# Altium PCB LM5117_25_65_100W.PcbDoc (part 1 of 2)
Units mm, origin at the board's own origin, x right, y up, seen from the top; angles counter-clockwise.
Board outline 73.02 x 159.13 mm, 4 copper layers (Top Layer, GND, Power, Bottom Layer), stack 0.742 mm thick; 149 components, 80 nets, 535 pads, 514 vias.
Unrouted connection lines stored in the file: 2.
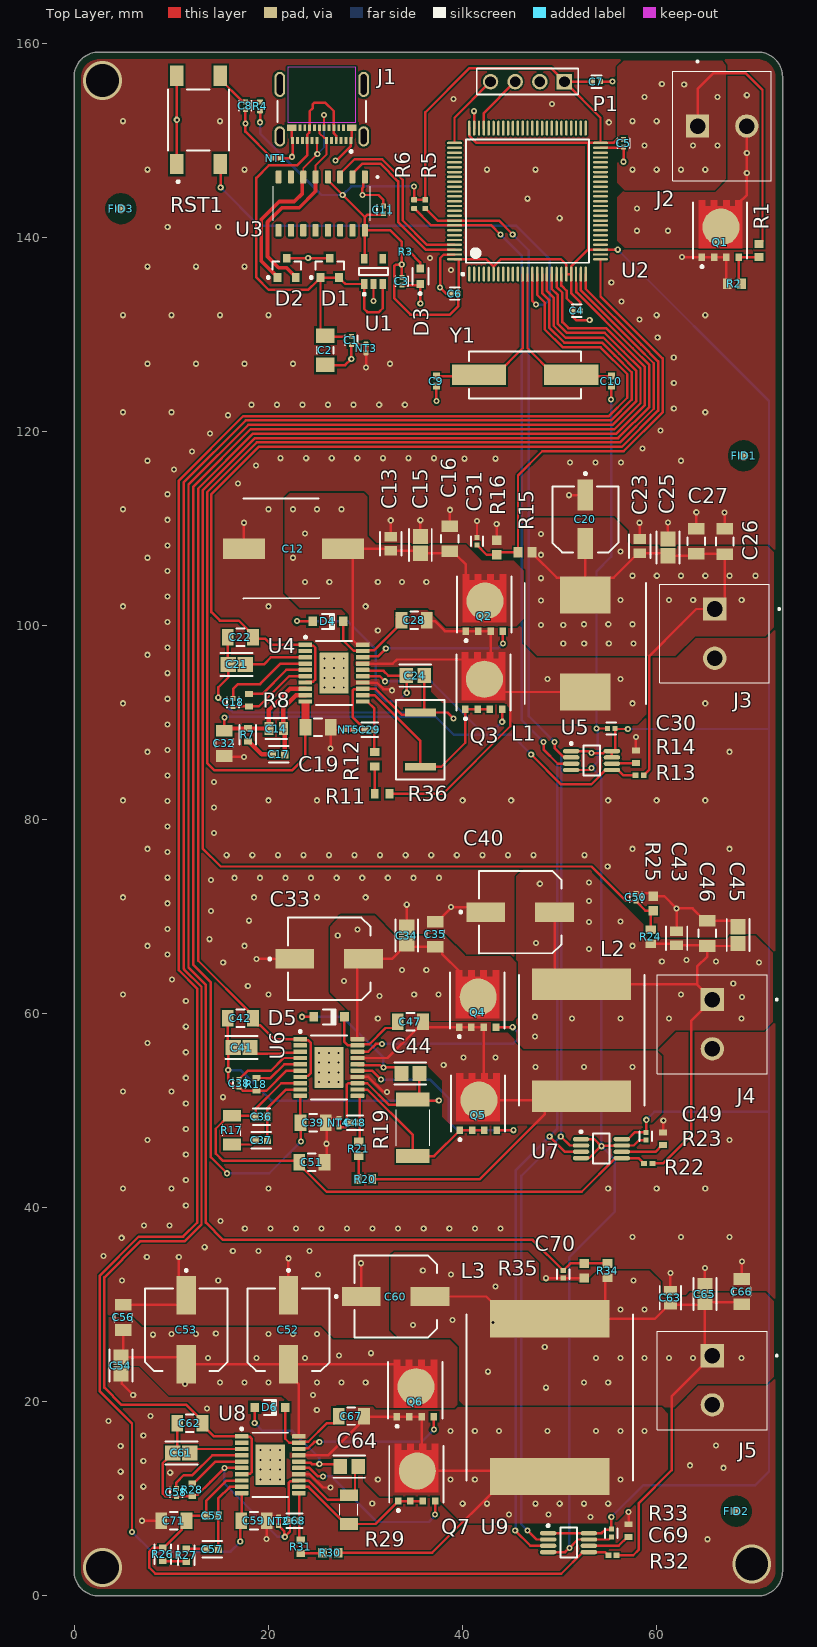
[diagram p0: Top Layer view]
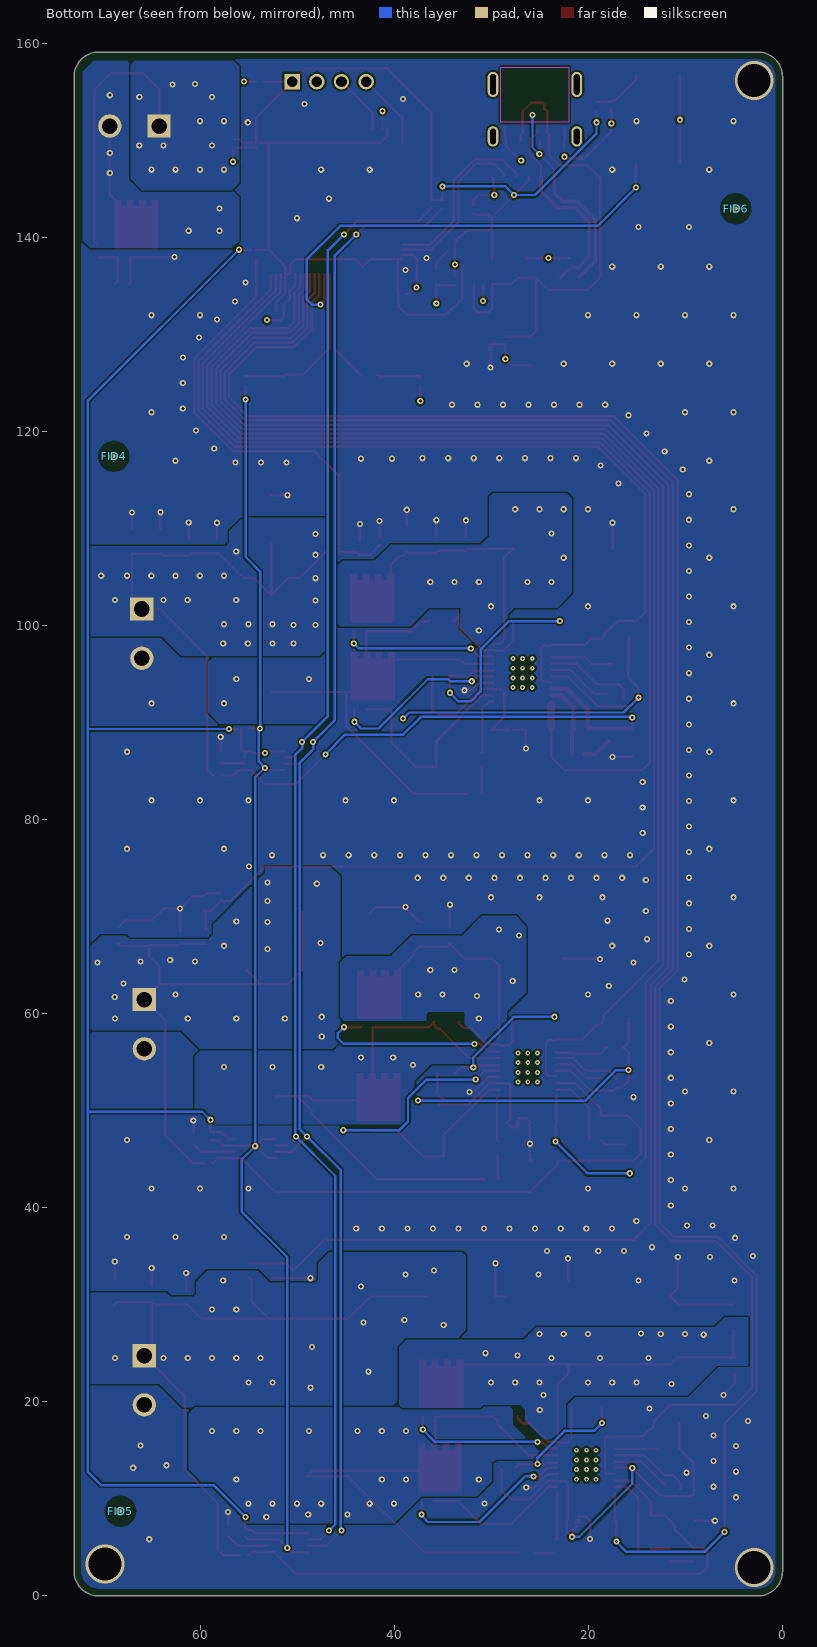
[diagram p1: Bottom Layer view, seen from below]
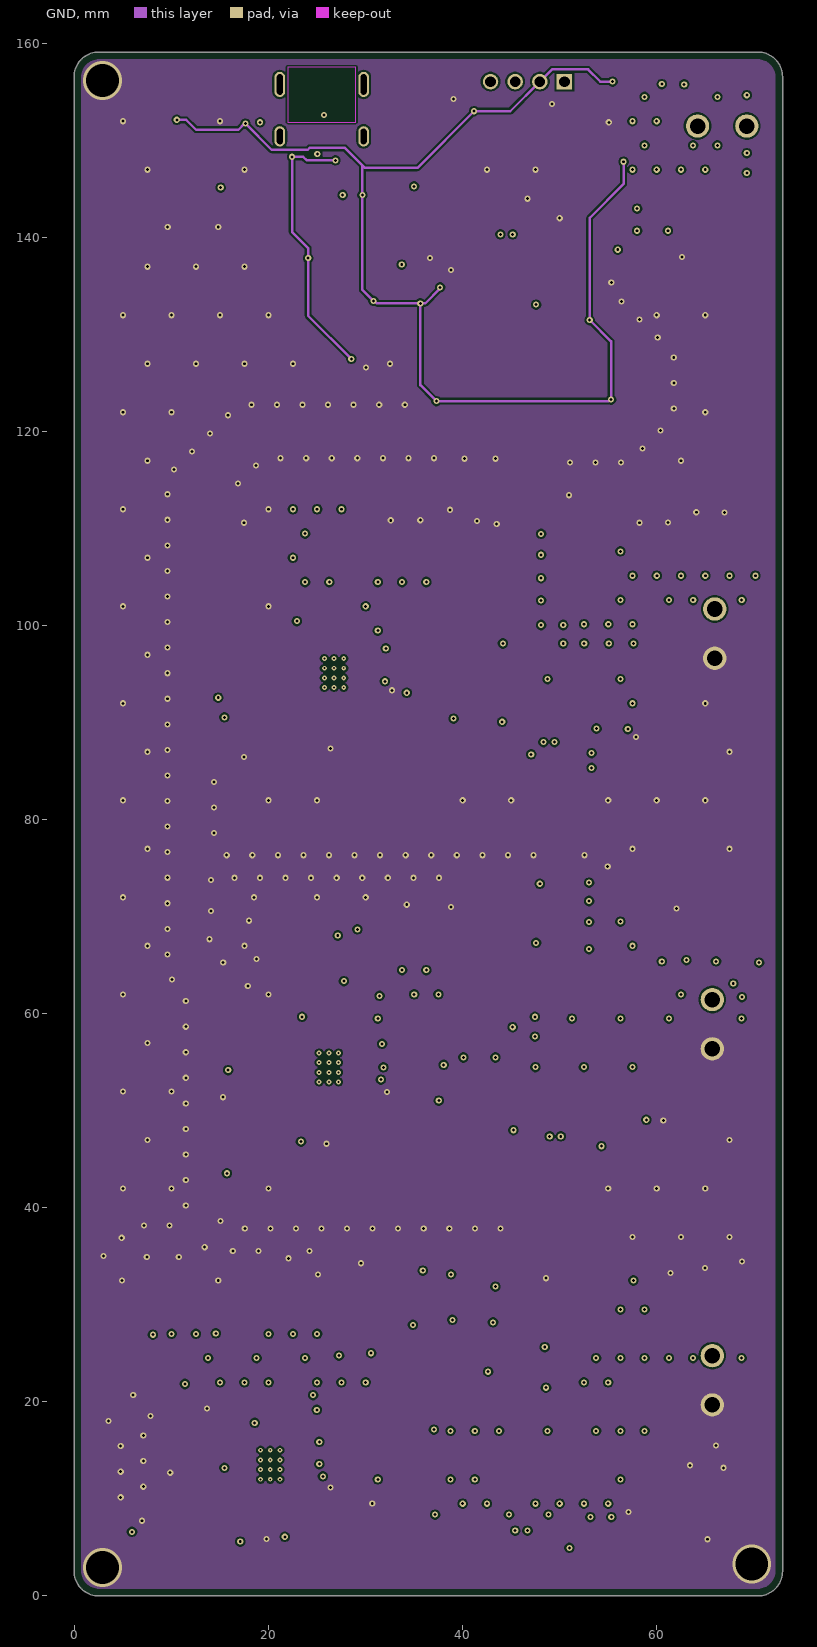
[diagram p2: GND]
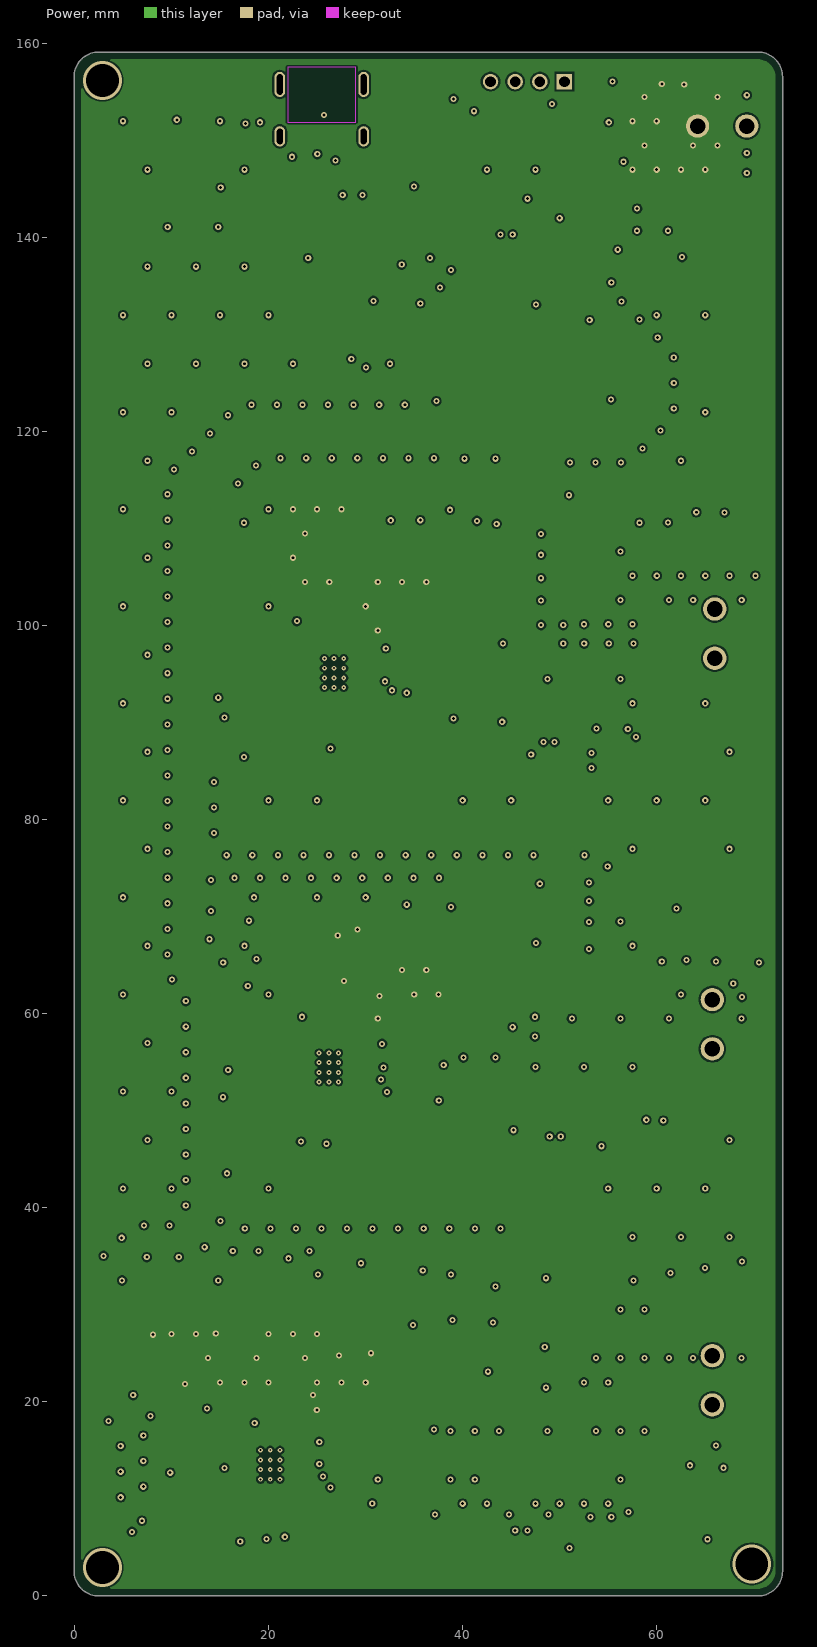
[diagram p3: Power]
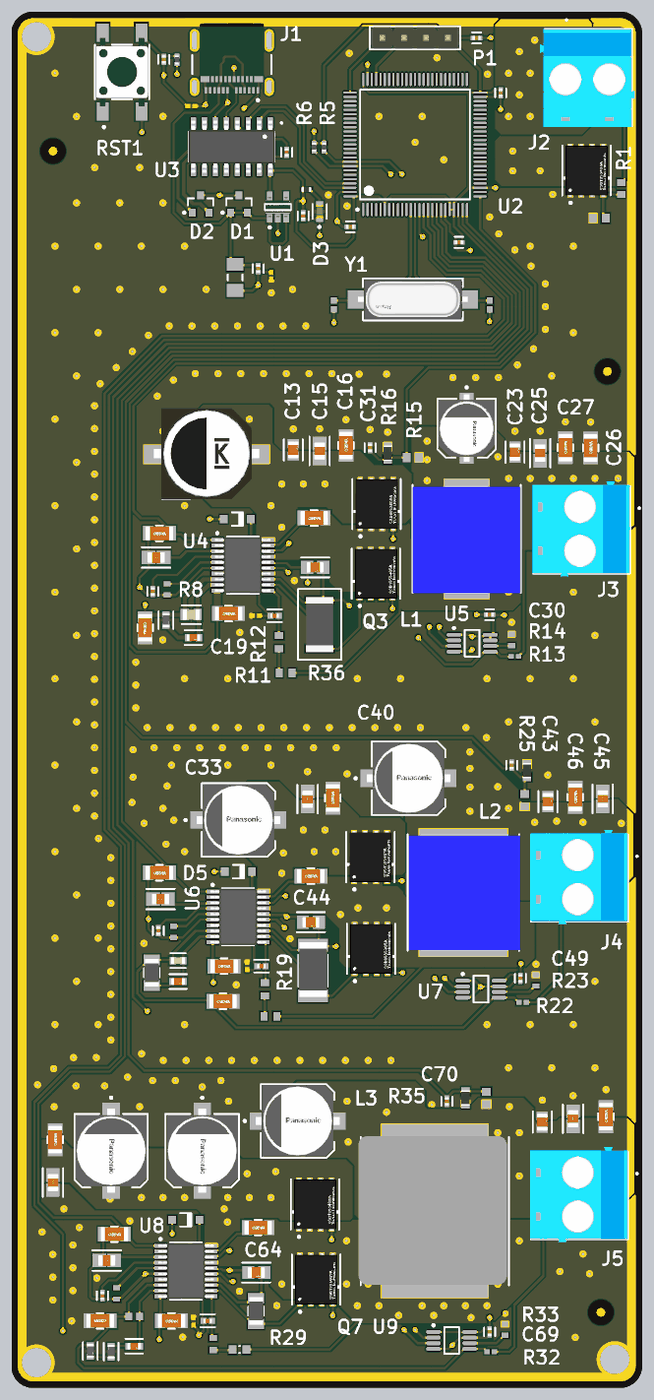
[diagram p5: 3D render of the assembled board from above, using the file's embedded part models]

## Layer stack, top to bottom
Top Solder: solder mask 0.0102, Solder Resist, Dk 3.5
Top Layer: signal copper 0.07
Dielectric 2: prepreg 0.0711, PP-006, Dk 4.1
GND: signal copper 0.07
Dielectric 1: dielectric 0.32, FR-4, Dk 4.8
Power: signal copper 0.07
Dielectric 3: prepreg 0.0711, PP-006, Dk 4.1
Bottom Layer: signal copper 0.07
Bottom Solder: solder mask 0.0102, Solder Resist, Dk 3.5

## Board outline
2.54,0 cw(c2.54,2.54) 0,2.54 0,156.591 cw(c2.54,156.591) 2.54,159.131 70.485,159.131 cw(c70.485,156.591) 73.025,156.591 73.025,2.54 cw(c70.485,2.54) 70.485,0

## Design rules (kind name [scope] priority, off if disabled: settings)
BoardOutlineClearance [All] p1: gap=0.75 ignorepadtopadclearanceinfootprint=FALSE
Clearance [All] p1: gap=0.2 ignorepadtopadclearanceinfootprint=TRUE
DiffPairsRouting [All] p1: maxlimit=0.254 minlimit=0.254 mostfreqgap=0.254 toplayer_minwidth=0.2 toplayer_maxwidth=0.381 toplayer_prefwidth=0.2 midlayer1_minwidth=0.2 midlayer1_maxwidth=0.381 midlayer1_prefwidth=0.381 midlayer2_minwidth=0.2 midlayer2_maxwidth=0.381 midlayer2_prefwidth=0.381 bottomlayer_minwidth=0.2 bottomlayer_maxwidth=0.381 bottomlayer_prefwidth=0.2 maxuncoupledlength=12.7
MinimumSolderMaskSliver [All] p1: minsoldermaskwidth=0.046
PlaneConnect [All] p1: planeconnectstyle=Direct reliefexpansion=0.508 reliefentries=4 reliefconductorwidth=0.254 reliefairgap=0.254
PolygonConnect [All] p1: connectstyle=Direct reliefconductorwidth=0.254 reliefentries=4 polygonreliefangle="90 Angle" airgapwidth=0.254
RoutingVias [All] p1: holewidth=0.711 width=1.27 viastyle="Through Hole" minholewidth=0.711 minwidth=1.27 maxholewidth=0.711 maxwidth=1.27
SilkToSolderMaskClearance [All] p1: minsilkscreentomaskgap=0.15 clearancetoexposedcopper=TRUE
SolderMaskExpansion [All] p1: expansion=0.102 istentingtop=FALSE
Width [All] p1: maxlimit=1 minlimit=0.254 preferedwidth=0.254
26 further rules are at their usual default settings.

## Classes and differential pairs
component class U_Programmer: C11 U3
component class "U_Power In": C1 C2 C3 D1 D2 D3 J1 J2 NT1 NT3 Q1 R1 R2 R3 U1
component class U_MCU: C4 C5 C6 C7 C8 C9 C10 P1 R4 R5 R6 RST1 U2 Y1
component class U_Buck_100W: C52 C53 C54 C55 C56 C57 C58 C59 C60 C61 C62 C63 C64 C65 C66 C67 C68 C69 C70 C71 D6 J5 L3 NT5 Q6 Q7 R26 R27 R28 R29 R30 R31 R32 R33 R34 R35 U8 U9
component class U_Buck_65W: C33 C34 C35 C36 C37 C38 C39 C40 C41 C42 C43 C44 C45 C46 C47 C48 C49 C50 C51 D5 J4 NT2 Q4 Q5 R17 R18 R19 R20 R21 R22 R23 R24 R25 U6 U7
component class U_Buck_25W: C12 C13 C14 C15 C16 C17 C18 C19 C20 C21 C22 C23 C24 C25 C26 C27 C28 C29 C30 C31 C32 D4 L1 NT2 Q2 Q3 R7 R8 R11 R12 R13 R14 R15 R16 R36 U4 U5
component class "Block Diagram": FID1 FID2 FID3 FID4 FID5 FID6
differential pair USB: +USB_P -USB_N

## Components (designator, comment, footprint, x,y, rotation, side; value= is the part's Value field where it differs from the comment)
C1 "C0402C104K4RACTU" FP-C0402-BB-MFG 28.575,129.413 r90 top value="0.10 μF"
C2 "C1206C105K3RACTU" CAPC3216X180X50ML20T25 25.908,128.397 r270 top
C3 "C0402C104K4RACTU" FP-C0402-BB-MFG 33.782,135.509 r90 top value="0.10 μF"
C4 "C0402C104K4RACTU" FP-C0402-BB-MFG 51.816,132.461 r0 top value="0.10 μF"
C5 "C0402C104K4RACTU" FP-C0402-BB-MFG 56.642,149.733 r90 top value="0.10 μF"
C6 "C0402C104K4RACTU" FP-C0402-BB-MFG 39.243,134.239 r0 top value="0.10 μF"
C7 "C0402C104K4RACTU" FP-C0402-BB-MFG 53.848,156.083 r180 top value="0.10 μF"
C8 "C0402C104K4RACTU" FP-C0402-BB-MFG 17.653,153.597 r90 top value="0.10 μF"
C9 "CC0402JRNPO9BN100" CAPC1005X55X25ML05T05 37.338,125.22 r270 top
C10 "CC0402JRNPO9BN100" CAPC1005X55X25ML05T05 55.372,125.222 r270 top
C11 "C0402C104K4RACTU" FP-C0402-BB-MFG 31.877,142.875 r270 top value="0.10 μF"
C12 "EDH476M100A9PAA" EDH476M100A9PAA 22.606,107.95 r180 top
C13 "GRM21BR61H475ME51L" FP-GRM21B-0_15-IPC_C 32.639,108.458 r90 top
C14 "C0805C680J5GAC" FP-C0805C-DN-MFG 20.828,89.408 r0 top value="68 pF"
C15 "C2012X7S2A105K125AB" FP-C2012-125-0_2-IPC_A 35.687,108.331 r90 top
C16 "CC1206KKX7R0BB104" FP-CC1206-0_3-1_45-IPC_C 38.735,108.966 r270 top
C17 "GCM188R72A682KA37D" FP-GCM188-0_1-IPC_C 21.082,86.741 r0 top
C18 "C0402C104K4RACTU" FP-C0402-BB-MFG 16.383,92.094 r270 top value="0.10 μF"
C19 "CC1206KKX7R0BB104" FP-CC1206-0_3-1_45-IPC_C 25.146,89.535 r180 top
C20 "EEE-FK1H100P" FP-FKD-MFG 52.705,110.958 r270 top
C21 "C2012X7S2A105K125AB" FP-C2012-125-0_2-IPC_A 16.764,96.012 r180 top
C22 "CC1206KKX7R0BB104" FP-CC1206-0_3-1_45-IPC_C 17.145,98.806 r180 top
C23 "GRM21BR61H475ME51L" FP-GRM21B-0_15-IPC_C 58.293,108.204 r90 top
C24 "GRM21BR72A474MA73L" FP-GRM21B-0_15-IPC_A 35.179,94.869 r0 top
C25 "C2012X7S2A105K125AB" FP-C2012-125-0_2-IPC_A 61.214,108.077 r90 top
C26 "CC1206KKX7R0BB104" FP-CC1206-0_3-1_45-IPC_C 67.056,108.682 r270 top
C27 "CC1206KKX7R0BB104" FP-CC1206-0_3-1_45-IPC_C 64.135,108.712 r270 top
C28 "CC1206KKX7R0BB104" FP-CC1206-0_3-1_45-IPC_C 35.052,100.584 r180 top
C29 "GCM155R72A821KA37J" FP-GCM155-0_05-IPC_A 30.48,89.281 r180 top
C30 "C0402C104K4RACTU" FP-C0402-BB-MFG 55.372,89.408 r180 top value="0.10 μF"
C31 "C0402C104K4RACTU" FP-C0402-BB-MFG 41.529,108.712 r270 top value="0.10 μF"
C32 "CC1206KKX7R0BB104" FP-CC1206-0_3-1_45-IPC_C 15.494,87.884 r90 top
C33 "EEE-TG2A220UP" FP-TGF-MFG 26.289,65.659 r0 top
C34 "C2012X7S2A105K125AB" FP-C2012-125-0_2-IPC_A 34.29,68.072 r90 top
C35 "CC1206KKX7R0BB104" FP-CC1206-0_3-1_45-IPC_C 37.211,68.199 r270 top
C36 "C0603C470J1GACTU" FP-C0603C-CF-MFG 19.304,49.403 r0 top value="47 pF"
C37 "GCM188R72A682KA37D" FP-GCM188-0_1-IPC_C 19.304,46.99 r0 top
C38 "C0402C104K4RACTU" FP-C0402-BB-MFG 17.018,52.851 r270 top value="0.10 μF"
C39 "CC1206KKX7R0BB104" FP-CC1206-0_3-1_45-IPC_C 24.638,48.768 r180 top
C40 "EEE-TG2A220UP" FP-TGF-MFG 45.974,70.485 r0 top
C41 "C2012X7S2A105K125AB" FP-C2012-125-0_2-IPC_A 17.272,56.515 r180 top
C42 "CC1206KKX7R0BB104" FP-CC1206-0_3-1_45-IPC_C 17.145,59.563 r180 top
C43 "GRM21BR61H475ME51L" FP-GRM21B-0_15-IPC_C 62.103,67.782 r90 top
C44 "GRM21BR72A474MA73L" FP-GRM21B-0_15-IPC_A 34.671,53.848 r0 top
C45 "C2012X7S2A105K125AB" FP-C2012-125-0_2-IPC_A 68.453,68.103 r90 top
C46 "CC1206KKX7R0BB104" FP-CC1206-0_3-1_45-IPC_C 65.278,68.29 r270 top
C47 "CC1206KKX7R0BB104" FP-CC1206-0_3-1_45-IPC_C 34.671,59.182 r180 top
C48 "GCM155R72A821KA37J" FP-GCM155-0_05-IPC_A 28.956,48.768 r180 top
C49 "C0402C104K4RACTU" FP-C0402-BB-MFG 58.928,47.371 r270 top value="0.10 μF"
C50 "C0402C104K4RACTU" FP-C0402-BB-MFG 57.912,72.009 r270 top value="0.10 μF"
C51 "CC1206KKX7R0BB104" FP-CC1206-0_3-1_45-IPC_C 24.511,44.704 r180 top
C52 "EEE-TG2A220UP" FP-TGF-MFG 22.098,27.432 r270 top
C53 "EEE-TG2A220UP" FP-TGF-MFG 11.557,27.432 r270 top
C54 "C2012X7S2A105K125AB" FP-C2012-125-0_2-IPC_A 4.826,23.749 r270 top
C55 "C0603C121J5GACTU" CAPC1608X87X35LL15T15 14.224,8.255 r0 top
C56 "CC1206KKX7R0BB104" FP-CC1206-0_3-1_45-IPC_C 5.08,28.702 r270 top
C57 "GCM188R72A682KA37D" FP-GCM188-0_1-IPC_C 14.224,4.826 r0 top
C58 "C0402C104K4RACTU" FP-C0402-BB-MFG 10.541,10.668 r270 top value="0.10 μF"
C59 "CC1206KKX7R0BB104" FP-CC1206-0_3-1_45-IPC_C 18.542,7.747 r180 top
C60 "EEE-TG2A220UP" FP-TGF-MFG 33.147,30.861 r0 top
C61 "C2012X7S2A105K125AB" FP-C2012-125-0_2-IPC_A 11.049,14.732 r180 top
C62 "CC1206KKX7R0BB104" FP-CC1206-0_3-1_45-IPC_C 11.938,17.78 r180 top
C63 "GRM21BR61H475ME51L" FP-GRM21B-0_15-IPC_C 61.468,30.734 r90 top
C64 "GRM21BR72A474MA73L" FP-GRM21B-0_15-IPC_A 28.358,13.335 r0 top
C65 "C2012X7S2A105K125AB" FP-C2012-125-0_2-IPC_A 65.024,31.115 r90 top
C66 "CC1206KKX7R0BB104" FP-CC1206-0_3-1_45-IPC_C 68.834,31.369 r270 top
C67 "CC1206KKX7R0BB104" FP-CC1206-0_3-1_45-IPC_C 28.575,18.542 r180 top
C68 "GCM155R72A821KA37J" FP-GCM155-0_05-IPC_A 22.733,7.747 r180 top
C69 "C0402C104K4RACTU" FP-C0402-BB-MFG 55.372,6.477 r270 top value="0.10 μF"
C70 "C0402C104K4RACTU" FP-C0402-BB-MFG 50.419,33.147 r90 top value="0.10 μF"
C71 "CC1206KKX7R0BB104" FP-CC1206-0_3-1_45-IPC_C 10.287,7.747 r0 top
D1 "SM15T1G" ONSC-SOT-23-3-318-08_V 26.35,136.89 r90 top
D2 "SM15T1G" ONSC-SOT-23-3-318-08_V 21.91,136.89 r90 top
D3 "150060VS75000" FP-150060VS75000-MFG 35.687,136.017 r90 top
D4 "1N4148W-7-F" DIOD-SOD123-2_V 26.162,100.457 r0 top
D5 "1N4148W-7-F" DIOD-SOD123-2_V 26.289,59.69 r0 top
D6 "1N4148W-7-F" DIOD-SOD123-2_V 20.193,19.431 r0 top
FID1 "FIDUCIAL" FIDUCIAL-ROUND 69.005,117.52 r0 top
FID2 "FIDUCIAL" FIDUCIAL-ROUND 68.243,8.732 r90 top
FID3 "FIDUCIAL" FIDUCIAL-ROUND 4.826,143.002 r90 top
FID4 "FIDUCIAL" FIDUCIAL-ROUND 68.929,117.452 r90 bottom
FID5 "FIDUCIAL" FIDUCIAL-ROUND 68.243,8.732 r90 bottom
FID6 "FIDUCIAL" FIDUCIAL-ROUND 4.826,143.002 r90 bottom
J1 "1054500101" FP-1054500101-MFG 25.527,153.797 r180 top locked
J2 "TB010-508-02BE" CUI_TB010-508-02BE 64.262,151.511 r0 top
J3 "TB010-508-02BE" CUI_TB010-508-02BE 66.04,101.727 r270 top
J4 "TB010-508-02BE" CUI_TB010-508-02BE 65.786,61.468 r270 top
J5 "TB010-508-02BE" CUI_TB010-508-02BE 65.786,24.765 r270 top
L1 "SRR1280-221K" SRR1280-221K 52.705,98.171 r90 top
L2 "IHLP5050EZER820M5A" IHLP5050EZER820M5A 52.324,57.277 r90 top
L3 "IHLP6767DZER470M11" IHLP6767DZER470M11 49.022,20.447 r90 top
NT1 "BOARD FEATURE" NETTIE-0.5X0.5X0.4 20.828,148.209 r0 top net-tie
NT2 "BOARD FEATURE" NETTIE-0.5X0.5X0.4 21.082,7.689 r90 top net-tie
NT3 "BOARD FEATURE" NETTIE-0.5X0.5X0.4 30.099,128.582 r270 top net-tie
NT4 "BOARD FEATURE" NETTIE-0.5X0.5X0.4 27.305,48.768 r90 top net-tie
NT5 "BOARD FEATURE" NETTIE-0.5X0.5X0.4 28.321,89.281 r180 top net-tie
P1 "61300411121" 61300411121 46.736,156.083 r180 top
Q1 "CSD19534Q5A" FP-DQJ0008A-MFG 66.605,140.747 r90 top
Q2 "CSD19534Q5AT" FP-DQJ0008A-MFG 42.291,102.193 r90 top
Q3 "CSD19534Q5AT" FP-DQJ0008A-MFG 42.221,94.138 r90 top
Q4 "CSD19534Q5AT" FP-DQJ0008A-MFG 41.586,61.372 r90 top
Q5 "CSD19534Q5AT" FP-DQJ0008A-MFG 41.656,50.758 r90 top
Q6 "CSD19534Q5AT" FP-DQJ0008A-MFG 35.179,21.209 r90 top
Q7 "CSD19534Q5AT" FP-DQJ0008A-MFG 35.306,12.531 r90 top
R1 "ERJ-3GEYJ104V" RESC1608X55X30NL15T15 70.612,138.684 r90 top
R2 "ERJ-3EKF2002V" RESC1608X55X30ML15T15 68.072,135.255 r0 top
R3 "ERJ-2RKF1000X" RESC1005X40X25LL05T05 34.163,138.557 r180 top
R4 "CRCW04023K30JNED" RESC1005X55N 19.177,153.543 r270 top value=3K3
R5 "CRCW04023K30JNED" RESC1005X55N 36.195,143.452 r270 top value=3K3
R6 "CRCW04023K30JNED" RESC1005X55N 35.052,143.452 r270 top value=3K3
R7 "RC0603FR-0736KL" FP-RC0603-0_55-IPC_C 17.907,88.773 r270 top
R8 "RC0603FR-0715KL" RESC1608X55X25LL10T15 18.034,92.329 r90 top
R11 "RC0603JR-07270KL" RESC1608X55X25ML10T15 31.75,82.677 r0 top
R12 "RC0603JR-1310KL" RESC1608X55X25ML10T15 30.988,86.233 r270 top
R13 "RC0402FR-0743KL" RESC1005X40X25NL05T10 58.293,84.582 r0 top
R14 "RC0603FR-0733RL" RESC1608X55X25LL10T15 57.912,86.487 r90 top
R15 "ERJ-3EKF1003V" RESC1608X55X30ML15T15 46.482,107.569 r0 top
R16 "ERJ-3EKF6801V" RESC1609X55X30NL15T15 43.561,108.065 r270 top
R17 "RC0603FR-0786K6L" PE1206FRM470R02L 16.256,48.006 r270 top value="86.6 kOhm"
R18 "RC0603FR-0715KL" RESC1608X55X25LL10T15 18.796,52.724 r90 top
R19 "PE2512FKE070R033L" PE2512FKE070R033L 34.925,48.255 r270 top value=33mOh
R20 "RC0603FR-10300KL" RESC1608X55X25ML10T15 29.987,42.968 r0 top
R21 "RC0603FR-103KL" RESC1608X55X25ML10T15 29.337,46.101 r270 top
R22 "RC0402FR-0743KL" RESC1005X40X25NL05T10 59.182,44.577 r0 top
R23 "RC0603FR-0733RL" RESC1608X55X25LL10T15 60.706,47.117 r90 top
R24 "ERJ-3EKF1003V" RESC1608X55X30ML15T15 59.436,67.945 r270 top
R25 "ERJ-3EKF6801V" RESC1609X55X30NL15T15 59.69,71.374 r270 top
R26 "RC0603FR-0736KL" FP-RC0603-0_55-IPC_C 9.144,4.276 r270 top
R27 "RC0603FR-071KL" FP-RC0603-0_55-IPC_C 11.557,4.191 r90 top
R28 "RC0603FR-0715KL" RESC1608X55X25LL10T15 12.192,10.922 r90 top
R29 "PE1206FRM470R02L" PE1206FRM470R02L 28.321,8.89 r270 top
R30 "RC0603FR-07270KL" RESC0603(1608)_N 26.416,4.445 r0 top value="270 kOhm"
R31 "RC0603FR-073KL" RESC1608X55X25NL10T15 23.368,5.08 r270 top
R32 "RC0402FR-0743KL" RESC1005X40X25NL05T10 55.499,4.191 r0 top
R33 "RC0603FR-0733RL" RESC1608X55X25LL10T15 57.15,6.731 r90 top
R34 "ERJ-3EKF1003V" RESC1608X55X30ML15T15 54.991,33.528 r270 top
R35 "ERJ-3EKF6801V" RESC1609X55X30NL15T15 52.578,33.528 r90 top
R36 "WSL2512R0900FEA" WSL2512R0900FEA 35.687,88.265 r270 top
RST1 "FSM2JSMAA" FP-FSM2JSMAA-MFG 12.827,152.146 r180 top
U1 "MIC5504-3.3YM5-TR" FP-SOT23-5LD-PL-1-MFG 30.861,136.525 r90 top
U2 "STM32F303VET7" STM-LQFP100_L 46.736,143.764 r90 top
U3 "CH340C" SOIC127P600X180-16N 25.527,143.51 r270 top
U4 "LM5117PMH/NOPB" PWP0020A_N 26.797,95.123 r0 top
U5 "MCP4552-502E/MS" MSOP-MS8_N 53.34,86.106 r0 top
U6 "LM5117PMH/NOPB" PWP0020A_N 26.259,54.469 r0 top
U7 "MCP4552-502E/MS" MSOP-MS8_N 54.356,46.101 r0 top
U8 "LM5117PMH/NOPB" PWP0020A_N 20.222,13.518 r0 top
U9 "MCP4552-502E/MS" MSOP-MS8_N 50.967,5.491 r0 top
Y1 "ABLS-8.000MHZ-B2-T" FP-ABLS-MFG 46.482,125.857 r180 top

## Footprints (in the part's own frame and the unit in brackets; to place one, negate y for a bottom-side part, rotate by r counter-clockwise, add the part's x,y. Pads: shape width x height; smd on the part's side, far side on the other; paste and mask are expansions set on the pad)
61300411121 [mm] "Pin Header, pitch 2.54 mm, THT, Vertical, single row, 4p"
  rect 1.6x1.6 hole 1.1: 1(-3.81,0)
  round 1.6 hole 1.1: 2(-1.27,0) 3(1.27,0) 4(3.81,0)
  silkscreen extent -5.23,-1.35 5.23,1.35, body extent -5.08,-1.27 5.08,1.27, height 8.57
CAPC1005X55X25ML05T05 [mm] "Chip Capacitor, 2-Leads, Body 1.00x0.50mm, IPC Low Density"
  rect 0.72x0.72 smd: 1(-0.51,0) 2(0.51,0)
  body extent -0.53,-0.28 0.53,0.27, height 0.55
CAPC1608X87X35LL15T15 [mm] "Chip Capacitor, 2-Leads, Body 1.60x0.80mm, IPC High Density"
  rect 0.8x0.9 smd: 1(-0.625,0) 2(0.625,0)
  body extent -0.87,-0.48 0.87,0.48, height 0.87
CAPC3216X180X50ML20T25 [mm] "Chip Capacitor, 2-Leads, Body 3.40x1.80mm, IPC Low Density"
  rect 1.5x1.9 smd: 1(-1.5,0) 2(1.5,0)
  silkscreen extent -0.35,-0.85 0.35,0.85, body extent -1.7,-0.9 1.7,0.9, height 1.8
CUI_TB010-508-02BE [mm]
  rect 2.4x2.4 / inner round 2.4 / far side rect 2.4x2.4 hole 1.6: 1(0,0)
  round 2.4 hole 1.6: 2(5.08,0)
  silkscreen extent -2.54,-5.66 7.62,6.74, body extent -3.07,-5.71 7.89,5.58, height 18.2
DIOD-SOD123-2_V [mm] "SOD123, 2-Leads, Body 2.7x1.55mm, Height 1.45mm"
  rect 0.9x0.95 smd: 1(-1.575,0) 2(1.575,0)
  silkscreen extent -0.64,-0.82 0.64,0.77, body extent -1.35,-0.77 1.35,0.77, height 1.45
EDH476M100A9PAA [mm]
  rect 4.35x2.1 smd: 1(-5.1,0) 2(5.1,0)
  silkscreen extent -2.67,-5.15 5.15,5.15, body extent -6.1,-5.33 6.1,5.17, height 10.51
FIDUCIAL-ROUND [mm] "BOARD FEATURE FIDUCIAL TARGET ROUND 1MM , 3MM CLEARANCE"
  round 1 smd paste-0.5 mask+1: 1(0,0)
  Top Layer pour cut-out: -0.025,-1.601 -0.632,-1.475 -1.144,-1.127 -1.484,-0.609 -1.6,0 -1.6,0 -1.478,0.612 -1.131,1.131 -0.612,1.478 0,1.6 0,1.6 0.612,1.478 1.131,1.131 1.478,0.612 1.6,0 1.6,0 1.473,-0.616 1.119,-1.137 0.593,-1.483 -0.025,-1.601
FP-150060VS75000-MFG [mm]
  rect 0.8x0.8 smd paste+0 mask+0: 1(-0.8,0) 2(0.8,0)
  silkscreen extent -1.9,-0.83 0.85,0.82, body extent -1.3,-0.55 1.3,0.55, height 0.25
FP-1054500101-MFG [mm]
  rrect100% 1.1x2.1 hole 1.6 slot 0.6 at 0 deg paste-1000 mask+0: 1(-4.32,3.36) 2(4.32,3.36)
  rrect100% 1.1x2.6 hole 2.1 slot 0.6 at 0 deg paste-1000 mask+0: 3(-4.32,-2) 4(4.32,-2)
  rect 0.3x0.7 smd paste+0 mask+0: A1(-3,3.77) A2(-2.5,3.77) A3(-2,3.77) A4(-1.5,3.77) A5(-1,3.77) A6(-0.5,3.77) A7(0.5,3.77) A8(1,3.77) A9(1.5,3.77) A10(2,3.77) A11(2.5,3.77) A12(3,3.77) B2(2.25,2.47) B3(1.75,2.47) B4(1.25,2.47) B5(0.75,2.47) B6(0.25,2.47) B7(-0.25,2.47) B8(-0.75,2.47) B9(-1.25,2.47) B10(-1.75,2.47) B11(-2.25,2.47)
  rect 1x0.7 smd paste+0 mask+0: B1(3.1,2.47) B12(-3.1,2.47)
  Keep-Out Layer region: -3.5,-3.77 3.5,-3.77 3.5,1.88 -3.5,1.88
  silkscreen extent -4.57,-0.3 4.57,5.03
FP-ABLS-MFG [mm]
  rect 5.6x2.1 smd paste+0 mask+0: 1(-4.75,0) 2(4.75,0)
  silkscreen extent -5.77,-2.42 5.77,2.42, body extent -7.65,-2.52 7.65,2.52, height 0.25
FP-C0402-BB-MFG [mm]
  rect 0.52x0.52 smd paste+0 mask+0: 1(-0.4,0) 2(0.4,0)
  silkscreen extent -0.5,-0.64 0.5,0.64, body extent -0.8,-0.4 0.8,0.4, height 0.25
FP-C0603C-CF-MFG [mm]
  rect 0.75x0.9 smd paste+0 mask+0: 1(-0.6,0) 2(0.6,0)
  silkscreen extent -0.87,-0.85 0.88,0.85, body extent -1.2,-0.6 1.2,0.6, height 0.25
FP-C0805C-DN-MFG [mm]
  rect 0.95x1.35 smd paste+0 mask+0: 1(-0.75,0) 2(0.75,0)
  silkscreen extent -1.1,-1.07 1.1,1.07, body extent -1.4,-0.85 1.4,0.85, height 0.25
FP-C2012-125-0_2-IPC_A [mm]
  rect 1.578x1.556 smd paste+0 mask+0: 1(-0.864,0) 2(0.864,0)
  silkscreen extent -1.65,-1.18 1.65,1.18, body extent -2.15,-1.28 2.15,1.28, height 0.25
FP-CC1206-0_3-1_45-IPC_C [mm]
  rect 1.203x1.706 smd paste+0 mask+0: 1(-1.3,0) 2(1.3,0)
  silkscreen extent -0.4,-0.9 0.4,0.9, body extent -2,-1 2,1, height 0.25
FP-DQJ0008A-MFG [mm]
  rect 0.75x0.675 smd paste-1000 mask+0: 1(-2.752,1.905) 2(-2.752,0.635) 3(-2.752,-0.635) 4(-2.752,-1.905)
  round 3.821 smd paste-1000 mask+0: 5-6-7-8(0.35,-0.07)
  Top Layer region: -1.823,2.242 3.127,2.242 3.127,1.568 2.472,1.568 2.472,0.972 3.127,0.972 3.127,0.298 2.472,0.298 2.472,-0.298 3.127,-0.298 3.127,-0.972 2.472,-0.972 2.472,-1.568 3.127,-1.568 3.127,-2.242 -1.823,-2.242 -1.823,2.242
  silkscreen extent -3.85,-2.78 2.9,2.82, body extent -3.23,-2.6 3.23,2.6, height 0.25
FP-FKD-MFG [mm]
  rect 3.2x1.6 smd paste+0 mask+0: 1(-2.5,0) 2(2.5,0)
  silkscreen extent -4.85,-3.4 3.4,3.4, body extent -4.35,-3.65 4.35,3.65, height 0.25
FP-FSM2JSMAA-MFG [mm]
  rect 1.38x2.1 smd paste+0 mask+0: 1(2.25,4.55) 2(2.24,-4.55) 3(-2.24,4.55) 4(-2.24,-4.55)
  silkscreen extent -3.15,-3.15 3.15,6.5, body extent -3.25,-5.7 3.25,5.7, height 0.25
FP-GCM155-0_05-IPC_A [mm]
  rect 0.715x0.672 smd paste+0 mask+0: 1(-0.479,0) 2(0.479,0)
  silkscreen extent -0.84,-0.74 0.84,0.74, body extent -1.04,-0.54 1.04,0.54, height 0.25
FP-GCM188-0_1-IPC_C [mm]
  rect 0.759x0.812 smd paste+0 mask+0: 1(-0.627,0) 2(0.627,0)
  silkscreen extent -1.01,-0.85 1.01,0.85, body extent -1.11,-0.55 1.11,0.55, height 0.25
FP-GRM21B-0_15-IPC_A [mm]
  rect 1.406x1.508 smd paste+0 mask+0: 1(-0.926,0) 2(0.926,0)
  silkscreen extent -1.63,-1.15 1.63,1.15, body extent -2.13,-1.25 2.13,1.25, height 0.25
FP-GRM21B-0_15-IPC_C [mm]
  rect 1.006x1.308 smd paste+0 mask+0: 1(-0.726,0) 2(0.726,0)
  silkscreen extent -1.23,-1.1 1.23,1.1, body extent -1.33,-0.8 1.33,0.8, height 0.25
FP-RC0603-0_55-IPC_C [mm]
  rect 0.659x0.812 smd paste+0 mask+0: 1(-0.677,0) 2(0.677,0)
  silkscreen extent -1.01,-0.85 1.01,0.85, body extent -1.11,-0.55 1.11,0.55, height 0.25
FP-SOT23-5LD-PL-1-MFG [mm]
  rect 1x0.66 smd paste+0 mask+0: 1(-1.3,0.95) 2(-1.3,0) 3(-1.3,-0.95) 4(1.3,-0.95) 5(1.3,0.95)
  silkscreen extent -2.47,-1.5 0.35,1.5, body extent -1.9,-1.6 1.9,1.6, height 0.25
FP-TGF-MFG [mm]
  rect 4x2 smd paste+0 mask+0: 1(-3.55,0) 2(3.55,0)
  silkscreen extent -6.25,-4.25 4.25,4.25, body extent -5.8,-4.5 5.8,4.5, height 0.25
IHLP5050EZER820M5A [mm]
  rect 3.25x10.2 smd: 1(-5.75,0) 2(5.75,0)
  silkscreen extent -6.73,-6.45 6.73,6.45, body extent -6.73,-6.58 6.73,6.32, height 5
IHLP6767DZER470M11 [mm]
  rect 3.825x12.32 smd: 1(-8.123,0) 2(8.123,0)
  silkscreen extent -8.57,-8.57 8.57,8.57, body extent -8.51,-8.34 8.67,8.84, height 3.9
MSOP-MS8_N [mm] "TSOP, 8-Leads, Body 3x3mm, Pitch 0.65mm, IPC Medium Density"
  oval 1.7x0.45 smd: 1(-2.1,0.975) 2(-2.1,0.325) 3(-2.1,-0.325) 4(-2.1,-0.975) 5(2.1,-0.975) 6(2.1,-0.325) 7(2.1,0.325) 8(2.1,0.975)
  silkscreen extent -2.22,-1.55 0.85,1.87, body extent -1.55,-1.55 1.55,1.55, height 1.1
NETTIE-0.5X0.5X0.4 [mm] "NET TIE 0.5 X 0.5MM PAD, 0.4MM GAP"
  rrect25% 0.5x0.5 smd paste-4 mask+0.076: 1(-0.45,0) 2(0.45,0)
  Top Layer region: -0.275,-0.25 0.25,-0.25 0.25,0.25 -0.275,0.25
ONSC-SOT-23-3-318-08_V [mm] "SOT23, 3-Leads, Body 2.92x1.3mm, Pitch 0.95mm"
  rect 0.9x0.8 smd: 1(-1,0.95) 2(-1,-0.95) 3(1,0)
  silkscreen extent -1.12,-1.46 0.65,2.02, body extent -0.65,-1.46 0.65,1.46, height 1.11
PE1206FRM470R02L [mm]
  rect 1.21x1.86 smd: 1(-1.476,0) 2(1.476,0)
  silkscreen extent -0.55,-0.93 0.55,0.93, body extent -1.6,-0.8 1.6,0.8, height 0.89
PE2512FKE070R033L [mm]
  rect 1.46x3.44 smd: 1(-2.926,0) 2(2.926,0)
  silkscreen extent -1.87,-1.72 1.87,1.72, body extent -3.3,-1.59 3.05,1.59, height 0.89
PWP0020A_N [mm] "SOP, 20-Leads, Body 6.6x4.5mm, Pitch 0.65mm, Thermal Pad 4.2x3mm, IPC Medium Density"
  rrect22% 1.4x0.45 smd: 1(-2.95,2.925) 2(-2.95,2.275) 3(-2.95,1.625) 4(-2.95,0.975) 5(-2.95,0.325) 6(-2.95,-0.325) 7(-2.95,-0.975) 8(-2.95,-1.625) 9(-2.95,-2.275) 10(-2.95,-2.925) 11(2.95,-2.925) 12(2.95,-2.275) 13(2.95,-1.625) 14(2.95,-0.975) 15(2.95,-0.325) 16(2.95,0.325) 17(2.95,0.975) 18(2.95,1.625) 19(2.95,2.275) 20(2.95,2.925)
  rrect3% 3x4.2 smd: 21(0,0)
  silkscreen extent -3.07,-3.3 1.85,3.82, body extent -3.21,-3.25 3.21,3.25, height 1
RESC0603(1608)_N [mm] "Chip Resistor, Body 1.6x0.8mm, IPC Medium Density"
  rect 0.9x1 smd: 1(-0.8,0) 2(0.8,0)
  silkscreen extent -0.05,-0.4 0.05,0.4, body extent -0.85,-0.47 0.85,0.47, height 0.6
RESC1005X40X25LL05T05 [mm] "Chip Resistor, 2-Leads, Body 1.05x0.55mm, IPC High Density"
  rect 0.45x0.45 smd: 1(-0.4,0) 2(0.4,0)
  body extent -0.53,-0.28 0.53,0.28, height 0.4
RESC1005X40X25NL05T10 [mm] "Chip Resistor, 2-Leads, Body 1.00x0.50mm, IPC Medium Density"
  rect 0.6x0.55 smd: 1(-0.425,0) 2(0.425,0)
  body extent -0.53,-0.27 0.53,0.28, height 0.4
RESC1005X55N [mm] "RESISTOR CHIP 0402 (1005) 0.55MM THICK"
  rrect25% 0.55x0.6 smd mask+0.075: 1(-0.45,0) 2(0.45,0)
  body extent -0.5,-0.25 0.5,0.25, height 0.27
RESC1608X55X25LL10T15 [mm] "Chip Resistor, 2-Leads, Body 1.70x0.90mm, IPC High Density"
  rect 0.6x0.8 smd: 1(-0.65,0) 2(0.65,0)
  body extent -0.85,-0.45 0.85,0.45, height 0.55
RESC1608X55X25ML10T15 [mm] "Chip Resistor, 2-Leads, Body 1.60x0.80mm, IPC Low Density"
  rect 0.8x1 smd: 1(-0.75,0) 2(0.75,0)
  body extent -0.85,-0.45 0.85,0.45, height 0.55
RESC1608X55X25NL10T15 [mm] "Chip Resistor, 2-Leads, Body 1.60x0.80mm, IPC Medium Density"
  rect 0.7x0.9 smd: 1(-0.7,0) 2(0.7,0)
  body extent -0.85,-0.45 0.85,0.45, height 0.55
RESC1608X55X30ML15T15 [mm] "Chip Resistor, 2-Leads, Body 1.60x0.80mm, IPC Low Density"
  rect 0.9x1.05 smd: 1(-0.725,0) 2(0.725,0)
  body extent -0.87,-0.48 0.87,0.48, height 0.55
RESC1608X55X30NL15T15 [mm] "Chip Resistor, 2-Leads, Body 1.60x0.80mm, IPC Medium Density"
  rect 0.8x0.95 smd: 1(-0.675,0) 2(0.675,0)
  body extent -0.87,-0.48 0.87,0.48, height 0.55
RESC1609X55X30NL15T15 [mm] "Chip Resistor, 2-Leads, Body 1.75x0.95mm, IPC Medium Density"
  rect 0.95x0.95 smd: 1(-0.75,0) 2(0.75,0)
  body extent -0.87,-0.48 0.87,0.48, height 0.55
SOIC127P600X180-16N [mm]
  rrect25% 1.31x0.62 smd: 1(-2.75,4.445) 2(-2.75,3.175) 3(-2.75,1.905) 4(-2.75,0.635) 5(-2.75,-0.635) 6(-2.75,-1.905) 7(-2.75,-3.175) 8(-2.75,-4.445) 9(2.75,-4.445) 10(2.75,-3.175) 11(2.75,-1.905) 12(2.75,-0.635) 13(2.75,0.635) 14(2.75,1.905) 15(2.75,3.175) 16(2.75,4.445)
  silkscreen extent -2.85,-5 1.78,5.85, body extent -3,-5 3,5, height 1.8
SRR1280-221K [mm]
  rect 3.8x5.2 smd: 1(-5,0) 2(5,0)
  silkscreen extent -6.25,-6.25 6.25,6.25, body extent -6.38,-6.25 6.12,6.25, height 8
STM-LQFP100_L [mm] "Thin QFP, 100-Leads, Body 14x14mm, Pitch 0.5mm, IPC High Density"
  oval 1.55x0.25 smd: 1(-7.525,6) 2(-7.525,5.5) 3(-7.525,5) 4(-7.525,4.5) 5(-7.525,4) 6(-7.525,3.5) 7(-7.525,3) 8(-7.525,2.5) 9(-7.525,2) 10(-7.525,1.5) 11(-7.525,1) 12(-7.525,0.5) 13(-7.525,0) 14(-7.525,-0.5) 15(-7.525,-1) 16(-7.525,-1.5) 17(-7.525,-2) 18(-7.525,-2.5) 19(-7.525,-3) 20(-7.525,-3.5) 21(-7.525,-4) 22(-7.525,-4.5) 23(-7.525,-5) 24(-7.525,-5.5) 25(-7.525,-6) 51(7.525,-6) 52(7.525,-5.5) 53(7.525,-5) 54(7.525,-4.5) 55(7.525,-4) 56(7.525,-3.5) 57(7.525,-3) 58(7.525,-2.5) 59(7.525,-2) 60(7.525,-1.5) 61(7.525,-1) 62(7.525,-0.5) 63(7.525,0) 64(7.525,0.5) 65(7.525,1) 66(7.525,1.5) 67(7.525,2) 68(7.525,2.5) 69(7.525,3) 70(7.525,3.5) 71(7.525,4) 72(7.525,4.5) 73(7.525,5) 74(7.525,5.5) 75(7.525,6)
  oval 0.25x1.55 smd: 26(-6,-7.525) 27(-5.5,-7.525) 28(-5,-7.525) 29(-4.5,-7.525) 30(-4,-7.525) 31(-3.5,-7.525) 32(-3,-7.525) 33(-2.5,-7.525) 34(-2,-7.525) 35(-1.5,-7.525) 36(-1,-7.525) 37(-0.5,-7.525) 38(0,-7.525) 39(0.5,-7.525) 40(1,-7.525) 41(1.5,-7.525) 42(2,-7.525) 43(2.5,-7.525) 44(3,-7.525) 45(3.5,-7.525) 46(4,-7.525) 47(4.5,-7.525) 48(5,-7.525) 49(5.5,-7.525) 50(6,-7.525) 76(6,7.525) 77(5.5,7.525) 78(5,7.525) 79(4.5,7.525) 80(4,7.525) 81(3.5,7.525) 82(3,7.525) 83(2.5,7.525) 84(2,7.525) 85(1.5,7.525) 86(1,7.525) 87(0.5,7.525) 88(0,7.525) 89(-0.5,7.525) 90(-1,7.525) 91(-1.5,7.525) 92(-2,7.525) 93(-2.5,7.525) 94(-3,7.525) 95(-3.5,7.525) 96(-4,7.525) 97(-4.5,7.525) 98(-5,7.525) 99(-5.5,7.525) 100(-6,7.525)
  silkscreen extent -7.65,-6.35 6.35,6.8, body extent -7,-7 7,7, height 1.6
WSL2512R0900FEA [mm]
  rect 0.8x3.2 smd: 1(-2.794,0) 2(2.794,0)
  silkscreen extent -4.09,-2.5 4.09,2.5, body extent -3.18,-1.59 3.18,1.59, height 0.64

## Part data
C1 C3 C4 C5 C6 C7 C8 C11 C18 C30 C31 C38 C49 C50 C58 C69 C70: library part CMP-2008-02108-2, "CAP CER 0.1UF 16V X7R 0402", Capacitance=100nF, Manufacturer=Kemet, Package=C0402-BB, Temperature="-55°C to +125°C", Temperature Characteristic=X7R, Temperature Coefficient=15%, Temperature Range High=+125°C, Temperature Range Low=-55°C, Tolerance=0.1, Voltage Rating="16 V"
C2: library part CMP-2000-04991-1, "Chip Capacitor, 1 uF, +/- 10%, 25 V, -55 to 125 degC, 1206 (3216 Metric), RoHS, Tape and Reel", Capacitance=1uF, Capacitance - nF=1000nF, Case Code - in=1206, Case Code - mm=3216, Case Height=1.6mm, Case Length=3.2mm, Dielectric=X7R, Manufacturer=Kemet, Maximum Operating Temperature=+125C, Minimum Operating Temperature=-55C, Operating Temperature Range=-55Cto+125C, Package / Case=1206(3216metric), Package Description="2-Pin Surface Mount Device, Body 3.2 x 1.6 mm", Temperature Coefficient / Code=+/-15%, Tolerance=10%, Voltage Rating=25V
C9 C10: library part CMP-2100-03589-1, "Chip Capacitor, 10 pF, +/- 5%, 50 V, -55 to 125 degC, 0402 (1005 Metric), RoHS, Tape and Reel", Capacitance=10pF, Case Code (Imperial)=0402, Case Code (Metric)=1005, Dielectric=C0G, Dielectric Material=Ceramic, Insulation Resistance=100GR, Manufacturer=Yageo, Max Operating Temperature=125degC, Min Operating Temperature=-55degC, Package Description="2-Pin Surface Mount Device, Body 1 x 0.5 mm", Package Quantity=1, Temperature Coefficient=30ppm/degC, Tolerance=5%, Voltage=50V
C12: "EDH, Aluminum, Aluminum Electrolytic, 47 uF, 20%, 100 VDC, -40/+105C, 105C, -40C, 105C, 2,000 Hrs, 18 % , 0.17, 47 uA, 2, 3, 10mm, 10.2mm, 500", Capacitance="47 uF", Manufacturer_Name=KEMET, Mouser Part Number=80-EDH476M100A9PAA, Voltage=100V
C13 C23 C43 C63: library part CMP-06035-037765-1, "Chip Multilayer Ceramic Capacitors for General Purpose, 0805, 4.7uF, X5R, 15%, 20%, 50V", Capacitance=4.7uF, Case Code (Imperial)=0805, Case Code (Metric)=2012, Dielectric=X5R, Max Operating Temperature=85°C, Min Operating Temperature=-55°C, Package Quantity=3000, Resistor Type=Ceramic, Tolerance=20%, Voltage Rating=50V
C14: library part CMP-03020-020862-1, "C0805 68 pF C0G 30ppm/°C 5.00% 50 V", Capacitance="68 pF", Manufacturer=KEMET, Package=C0805C-DN, Temperature="-55°C to +125°C", Temperature Characteristic=C0G, Temperature Coefficient=30ppm/°C, Temperature Range High=+125°C, Temperature Range Low=-55°C, Tolerance=0.05, Voltage Rating="50 V"
C15 C21 C25 C34 C41 C45 C54 C61 C65: library part CMP-2000-05454-2, "Multilayer Ceramic Capacitors 1μF ±10% 100V X7S SMD 0805", Capacitance=1uF, Case Code (Imperial)=0805, Case Code (Metric)=2012, Dielectric=X7S, Max Operating Temperature=125°C, Min Operating Temperature=-55°C, Package Quantity=1, Resistor Type=Ceramic, Tolerance=10%, Voltage=100V
C16 C19 C22 C26 C27 C28 C32 C35 C39 C42 C46 C47 C51 C56 C59 C62 C66 C67 C71: library part CMP-03422-001499-1, "CAP CER 0.1UF 100V X7R 1206", Capacitance=100nF, Case Code (Imperial)=1206, Case Code (Metric)=3216, Dielectric=X7R, Dielectric Material=Ceramic, Max Operating Temperature=125°C, Min Operating Temperature=-55°C, Package Quantity=1, Tolerance=10%, Voltage Rating=100V
C17 C37: library part CMP-2006-02398-2, "Ceramic Capacitor for Automotive 6.8nF  ±10% 100VDC X7R 0603 Paper T/R", Capacitance=6.8nF, Case Code (Imperial)=0603, Case Code (Metric)=1608, Dielectric=X7R, Max Operating Temperature=125°C, Min Operating Temperature=-55°C, Package Quantity=4000, Ratings=AEC-Q200, Tolerance=10%, Voltage Rating=100V
C20: library part CMP-2000-06207-2, "CAP ALUM 10UF 20% 50V SMD", Capacitance=10uF, Case/Package=Radial, ESR (Equivalent Series Resistance)=880mR, Leakage Current=3uA, Max Operating Temperature=105°C, Min Operating Temperature=-55°C, Package Quantity=1000, Ripple Current=165mA, Tolerance=20%, Voltage=50V
C24 C44 C64: library part CMP-06035-021373-1, "Chip Multilayer Ceramic Capacitors for General Purpose, 0805, 0.47uF, X7R, 15%, 20%, 100V", Capacitance=470nF, Case/Package=0805, Dielectric=X7R, Tolerance=20%, Voltage Rating (DC)=100V
C29 C48 C68: library part CMP-06035-060413-1, "Ceramic Capacitor for Automotive 820pF ±10% 100VDC X7R 0402 Paper T/R", Capacitance=820pF, Voltage=100V
C33 C40 C52 C53 C60: library part CMP-05427-002105-1, "CAP ALUM 22UF 20% 100V SMD", Capacitance=22uF, Case/Package=Radial, ESR (Equivalent Series Resistance)=1.3R, Max Operating Temperature=125°C, Min Operating Temperature=-40°C, Package Quantity=500, Ratings=AEC-Q200, Ripple Current=70mA, Tolerance=20%, Voltage=100V
C36: library part CMP-2006-03321-2, "CAP CER 47PF 100V 5% NP0 0603", Capacitance="47 pF", Manufacturer=KEMET, Package=C0603C-CF, Temperature="-55°C to +125°C", Temperature Characteristic=C0G, Temperature Coefficient=30ppm/°C, Temperature Range High=+125°C, Temperature Range Low=-55°C, Tolerance=0.05, Voltage Rating="100 V"
C55: library part CMP-2006-03074-1, "SMD/SMT 50V 120pF C0G 0603 5%", Capacitance="120 pF", Manufacturer=Kemet, Voltage="50 V"
C57: library part CMP-2006-02398-2, "6.8 nF 100 VDC 10% 0603 X7R", Capacitance=6.8nF, Case Code (Imperial)=0603, Case Code (Metric)=1608, Dielectric=X7R, Max Operating Temperature=125°C, Min Operating Temperature=-55°C, Package Quantity=4000, Ratings=AEC-Q200, Tolerance=10%, Voltage Rating=100V
D1 D2: library part CMP-1061-00669-1, "Transient Voltage Suppressor Diode Array, Dual Common Anode Diodes for ESD Protection, 3-Pin SOT-23, Pb-Free, Tape and Reel", Manufacturer="On Semiconductor"
D3: library part CMP-1426-00006-5, "LED GREEN CLEAR 0603 SMD", Case Code (Imperial)=0603, Case Code (Metric)=1608, Color=Green, Forward Current=20mA, Forward Voltage=2V, Lens Color=Colorless, Max Operating Temperature=85°C, Min Operating Temperature=-40°C, Package Quantity=4000, Power Rating=72mW, Reverse Voltage (DC)=5V
D4 D5 D6: library part CMP-2000-04932-2, "Fast Switching Diode, 100 V, 0.15 A, -65 to 150 degC, 2-Pin?SOD123, RoHS, Tape and Reel", If - Forward Current=0.15A, Ir - Reverse Current=1uA, Manufacturer=DiodesIncorporated, Max Surge Current=2A, Maximum Operating Temperature=+150C, Minimum Operating Temperature=-65C, Operating Temperature Range=-65Cto+150C, Package / Case=SOD-123, Package Reference=SOD123-2, Peak Reverse Voltage=100V, Vf - Forward Voltage=1.25V
FID1 FID2 FID3 FID4 FID5 FID6: library part CMP-00005-9, "FIDUCIAL,1MM, 3MM CLEARANCE", Part Number=BOARD_FEATURE
J1: library part CMP-04767-000004-1, "CONN RCP USB3.1 TYPEC 24P SMD RA", Current Rating=0.25/1.25/5A, Manufacturer=Molex, Package=0, Temperature="-30°C to +85°C", Temperature Range High=+85°C, Temperature Range Low=-30°C, Voltage Rating=30V
J2 J3 J4 J5: "2~24 Poles, Screw Type, Horizontal, 5.08 Pitch, 26~12 (AWG), Terminal Block Connector", Package=None
L1: "Bourns SRR1280 Series Shielded Wire-wound SMD Inductor with a Ferrite Core, 220 uH +/-10% Wire-Wound 1.6A Idc Q:24", Inductance="220 uH", Manufacturer_Name=Bourns, Mouser Part Number=652-SRR1280-221K
L2: "Fixed Inductors 82uH 20% High Temp AEC-Q200", Inductance="82 uH", Manufacturer_Name=Vishay, Max DC current=3A, Max DC resistance="201 mOhms", Max Saturation Current=3.1A, Mouser Part Number=70-IHLP5050EZR820M5A, Tolerence=20%
L3: "Fixed Inductors 47uH 20% Shielded", Inductance=47uH, Manufacturer_Name=Vishay, Max DC current=5A, Max DC resistance=108mOhm, Saturation Current=4.3A
NT1 NT2 NT3 NT4 NT5: library part CMP-01115-6, "NET TIE 0.5 x 0.5 mm, 0.4mm GAP", Manufacturer=TESLA, Manufacturer PartNo="NONE - BOARD FEATURE"
P1: library part CMP-1502-01064-1, "THT Vertical Pin Header WR-PHD, Pitch 2.54 mm, Single Row, 4 pins", Contact Resistance=20mOhm, Manufacturer="Wurth Elektronik", Operating Temperature=-40to105degC, Rated Current=3A, Withstanding Voltage=500VAC, Working Voltage=250VAC
Q1 Q2 Q3 Q4 Q5 Q6 Q7: library part CMP-04962-000018-1, "MOSFET N-CH 100V 50 8SON", Continuous Drain Current=10A, Drain To Source Breakdown Voltage=100V, Drain To Source Resistance=12.6mΩ, Gate To Source Voltage=20V, Input Capacitace At Vds="1290pF @ 50V", Manufacturer="Texas Instruments", Max Forward Diode Voltage=1V, Max Junction Temp=+150°C, Package=DQJ0008A, Power Dissipation=3.2W, Pulse Drain Current=137A, Temperature="-55°C to +150°C", Temperature Range Low=-55°C, Typ Forward Diode Voltage=0.8V
R1: library part CMP-2000-00705-1, Manufacturer=Panasonic, Resistance=100kOhm, Voltage=75V
R2: library part CMP-2000-00318-1, Manufacturer=Panasonic, Resistance=20kOhm, Voltage=75V
R3: library part CMP-2002-00605-3, "Chip Resistor, 100 Ohm, +/- 1%, 100 mW, -55 to 155 degC, 0402 (1005 Metric), RoHS, Tape and Reel", Case Code (Imperial)=0402, Case Code (Metric)=1005, Manufacturer="Basic Passives", Max Operating Temperature="155 degC", Min Operating Temperature="-55 degC", Package Quantity=10000, Power Rating="100 mW", Resistance="100 Ohm", Tolerance=1%, Voltage Rating="50 V"
R4 R5 R6: library part CMP-03871-5, "RES,3K3,1/16W,5%,0402(1005),AEC-Q", Manufacturer=VISHAY, Package="0402 (1005)", Part Notes=M3, Part Number=1112821-00-A, Tolerance=5%
R7 R26: library part CMP-03412-037824-1, "RES 36K OHM 1% 1/10W 0603", Case Code (Imperial)=0603, Case Code (Metric)=1608, Max Operating Temperature=155°C, Max Power Dissipation=100mW, Min Operating Temperature=-55°C, Package Quantity=1, Resistance="36 kOhm", Resistor Type="Thick Film", Temperature Coefficient=100ppm/°C, Tolerance=1%, Voltage Rating=75V, Voltage Rating (DC)=50V
R8 R18 R28: library part CMP-1659-00032-1, "Chip Resistor, 15 KOhm, +/- 1%, 0.1 W, -55 to 155 degC, 0603 (1608 Metric), RoHS, Tape and Reel", Resistance="15 KOhm", Voltage="75 V"
R11: library part CMP-2000-04314-1, "Thick Film Resistors - SMD 270 kOhms 100 mW 0603 5%", Manufacturer=Yageo, Part Number=RC0603JR-1310KL, Resistance="270 kOhms", Voltage=75V
R12: library part CMP-2000-04314-1, "Thick Film Resistors - SMD 10 kOhms 100-200 mW 0603 5%", Manufacturer=Yageo, Resistance="10 kOhms", Voltage=75V
R13 R22 R32: library part CMP-1011-00694-2, "Thick Film Resistors - SMD 43 kOhms 62.5mW 0402 1%", Manufacturer="Yageo / Phycomp", Power="62.5 mW", Resistance="43 kOhm", Tolerence=1%, Voltage="50 V"
R14 R23 R33: library part CMP-2000-06939-1, "Chip Resistor, 33 Ohm, +/- 1%, 0.1 W, -55 to 155 degC, 0603 (1608 Metric), RoHS, Tape and Reel", Case Code - in=0603, Case Code - mm=1608, Manufacturer=Yageo, Operating Temperature Range=-55Cto+155C, Package / Case=0603(1608metric), Package Description="2-Pin Surface Mount Device, Body 1.6 x 0.8 mm", Power Rating=100mW, Resistance=33Ohms, Temperature Coefficient=100PPM/C, Tolerance=1%, Voltage Rating=75V
R15 R24 R34: library part CMP-2000-00182-1, Manufacturer=Panasonic, Resistance=100kOhm, Tolerence=1%, Voltage=75V
R16 R25 R35: library part CMP-1012-00604-3, "Chip Resistor, 6.8 KOhm, +/- 1%, 0.1 W, -55 to 155 degC, 0603 (1608 Metric), RoHS, Tape and Reel", Manufacturer PartNo=ERJ-3EKF6800V, Resistance=6.8kOhm, Tolerence=1%, Voltage=75V
R17: "SMD 86.6 kOhms 100 mW 0603 1%", Power="100 mW", Tolerence=1%
R19: "SMD 33 mOhms 1 Watts 1 % 50 ppm/C", Power=1W, Tolerence=1%
R20: library part CMP-2000-04314-1, "Thick Film Resistors - SMD 300kOhms 1/10W 0603 1%", Manufacturer=Yageo, Power="100 mW", Resistance="300 kOhms", Voltage=75V
R21: library part CMP-2000-04314-1, "Thick Film Resistors - SMD 3 kOhms 100 mW 0603 1%", Manufacturer=Yageo, Resistance="3 kOhm", Voltage=75V
R27: library part CMP-1659-00009-5, "RES 1K OHM 1% 1/10W 0603", Case Code (Imperial)=0603, Case Code (Metric)=1608, Max Operating Temperature=155°C, Max Power Dissipation=100mW, Min Operating Temperature=-55°C, Resistance="1 kOhm", Resistance Tolerance=1%, Resistor Type="Thick Film", Temperature Coefficient=100ppm/°C, Voltage Rating=50V
R29: "SMD 20 mOhms 1 Watts 1 % 75 ppm/C", Power="1 W", Resistance="20 mOhm", Tolerence="1 %"
R30: library part CMP-1012-00783-1, "SMD 270 kOhms 100mW 0603 1%", Case-EIA=0603, Case-Metric=1608, Power="0.1 W", Tolerance="1 %", Voltage=75V
R31: library part CMP-2000-04040-1, "SMD 3 kOhms 100mW 0603 1%", Manufacturer=Yageo, Power="100 mW", Resistance="3 kOhms", Tolerence=1%, Voltage=75V
R36: "SMD 1watt 90 mOhms 1%", Power="1 W", Resistance="90 mOhms"
RST1: library part CMP-03402-000003-1, "SWITCH TACTILE SPST-NO 0.05A 24V", Contact Current Rating=50mA, Contact Resistance=100mΩ, Manufacturer="TE Connectivity", Operating Force=260gf, Package=0, Temperature="-35°C to +85°C", Temperature Range High=+85°C, Temperature Range Low=-35°C, Voltage Rating DC=24V
U1: library part CMP-2000-07604-2, "IC REG LINEAR 3.3V 300MA SOT23-5", Case/Package=SOT-23-5, Dropout Voltage=380mV, Max Input Voltage=5.5V, Max Operating Temperature=125°C, Max Output Current=300mA, Min Input Voltage=2.5V, Min Operating Temperature=-40°C, Nominal Output Voltage=3.3V, Operating Supply Current=42uA, Power Supply Rejection Ratio (PSRR)=60dB, Quiescent Current=38uA
U2: library part CMP-0537-00059-1, "ARM Cortex-M4 32-bit MCU, 512 KB Flash, 80 KB Internal RAM, 86 I/Os, 100-Pin LQFP, -40 to 105 degC, Tray", I/Os (High Current)=86, Operating Frequency(F) (Processor speed) (MHz)=72, Package Description="100-Pin Low Profile Quad Flat Package, Body 14 x 14 mm, Pitch 0.5 mm", Package Reference=LQFP100, Supply Voltage(Vcc) min (V)=2
U3: "USB to serial chip CH340", Package=None
U4 U6 U8: library part CMP-0069-02227-2, "Wide Input Range Synchronous Buck Controller with Analog Current Monitor, 20-pin TSSOP-EP, 73 Rail", Manufacturer="Texas Instruments", PackageTopMarking=NSUZXYTT*LM5117*PMH, PowerWise=Y
U5 U7 U9: library part CMP-0188-00827-2, "8-Bit Single I2C Digital POT with Volatile Memory, 8-pin MSOP, Extended Temperature"
Y1: library part CMP-27762-009874-1, "CRYSTAL 8.0000MHZ 18PF SMD", Case/Package=SMD/SMT, ESR (Equivalent Series Resistance)=80R, Frequency=8MHz, Frequency Stability=50ppm, Frequency Tolerance=20ppm, Load Capacitance=18pF, Max Operating Temperature=70°C, Min Operating Temperature=-20°C, Operating Frequency="8 MHz", Package Quantity=1000

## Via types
v1: diameter 0.635, hole 0.305, Top Layer to Bottom Layer, 475 vias
v2: diameter 0.5, hole 0.2, Top Layer to Bottom Layer, 36 vias
v3: diameter 4, hole 3.4, Top Layer to Bottom Layer, 3 vias

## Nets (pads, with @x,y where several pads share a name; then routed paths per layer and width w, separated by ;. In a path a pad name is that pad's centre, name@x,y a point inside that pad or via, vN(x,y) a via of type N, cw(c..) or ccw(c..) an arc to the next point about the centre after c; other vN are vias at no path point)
3V3: C3.2 C4.2 C5.2 C6.2 C7.2 C11.2 C30.1 C49.1 C69.1 P1.1 R3.2 R4.2 R5.1 R6.1 U1.5 U2.6 U2.21 U2.22 U2.28 U2.50 U2.75 U2.100 U3.4 U3.16 U5.1 U5.7 U5.8 U7.8 U9.1 U9.8 | length 348
  Top Layer w0.254: v1(19.177,151.892) R4.2@19.177,153.093 ; U3.4@26.162,146.26 26.162,145.915 29.972,142.105 ; U1.5@29.911,137.825 29.941,137.856 U3.16@29.941,140.76 ; C11.2@31.877,142.475 31.744,142.342 30.201,142.342 29.972,142.113 29.972,142.105 ; C3.2@33.782,135.909 33.773,135.918 v1(33.773,137.233) ; v1(35.052,145.288) R6.1@35.052,143.902 R5.1@36.195,143.902 36.195,152.908 40.767,157.48 49.149,157.48 P1.1@50.546,156.083 ; U2.100@39.211,137.764 U2.100@39.641,137.764 ; U2.75@40.736,151.289 40.738,151.287 40.738,150.498 41.472,149.764 52.959,149.764 ; U9.1@48.867,6.466 U9.8@53.067,6.466 54.371,6.466 54.731,6.825 55.32,6.825 C69.1@55.372,6.877 v1(55.372,8.128) ; U5.1@51.24,87.081 53.024,87.081 53.237,86.868 54.568,86.868 54.781,87.081 U5.8@55.44,87.081 ; C4.2@52.216,132.461 52.193,132.484 52.193,133.333 51.238,134.288 U2.22@51.236,136.239 U2.22@51.236,136.239 ; C7.2@53.448,156.083 P1.1@50.546,156.083 ; U2.28@54.261,138.764 52.972,138.764 ; U2.28@54.789,138.759 v1(56.04,138.759) ; U5.7@55.44,86.431 U5.8@55.44,87.081 ; C30.1@55.772,89.408 55.772,87.172 55.681,87.081 U5.8@55.44,87.081 ; C30.1@55.824,89.356 v1(57.075,89.356) ; U7.8@56.456,47.076 57.081,47.076 57.776,47.771 C49.1@58.928,47.771 ; C5.2@56.642,150.133 55.96,150.133 55.591,149.764 U2.50@54.261,149.764 ; C49.1@58.98,47.823 v1(58.98,49.074) ; 29.972,142.105 U3.16@29.972,140.76 32.595,140.76 33.763,139.592 R3.2@33.763,138.557 33.773,138.547 v1(33.773,137.233) ; v1(33.773,137.233) 33.169,137.233 33.02,137.084 33.02,133.731 34.671,132.08 38.735,132.08 39.612,132.957 39.612,134.208 C6.2@39.643,134.239 39.643,137.762 U2.100@39.641,137.764 ; U2.100@39.641,137.764 42.5,137.764 43.234,137.03 43.999,137.795 50.165,137.795 50.734,137.226 50.734,136.241 U2.21@50.736,136.239 U2.22@51.236,136.239 ; P1.1@50.546,156.083 54.261,152.368 U2.50@54.261,149.764 ; U2.22@51.236,136.239 51.238,136.241 51.238,137.03 52.972,138.764 ; 52.959,149.764 U2.50@54.261,149.764 ; 52.959,149.764 52.972,149.751 52.972,138.764
  Bottom Layer w0.254: v1(19.177,151.892) 19.177,150.727 25.505,144.399 v1(27.686,144.399) 28.575,145.288 v1(35.052,145.288) ; v1(55.372,8.128) 58.674,11.43 70.231,11.43 71.628,12.827 71.628,49.911 ; v1(56.04,138.759) 71.628,123.171 71.628,89.356 ; v1(57.075,89.356) 71.628,89.356 ; v1(58.98,49.074) 59.817,49.911 71.628,49.911 ; 71.628,49.911 71.628,89.356
  other v1: 53.34,86.868
5V: C1.2 C2.1 D1.1 D1.2 J1.A4 J1.A9 J1.B4 J1.B9 U1.1 U1.3 | length 56.4
  Top Layer w0.254: J1.A4@27.027,150.027 27.004,150.05 27.004,150.512 26.777,150.739 J1.B9@26.777,151.327 26.777,153.027 25.908,153.896 25.908,153.924 24.765,153.924 24.585,153.744 24.585,153.335 24.277,153.027 J1.B4@24.277,151.327 24.254,151.304 24.254,150.842 24.027,150.615 J1.A9@24.027,150.027 24.027,148.487 22.987,147.447 20.066,147.447 18.787,146.168 18.787,135.899 20.066,134.62 24.13,134.62 25.077,135.567 25.127,135.567 25.4,135.84 D1.1@25.4,135.89 ; C1.2@28.575,129.813 25.992,129.813 C2.1@25.908,129.897 25.4,130.405 D1.1@25.4,135.89 ; U1.3@31.811,135.225 31.811,132.722 31.423,132.334 30.226,132.334 29.911,132.649 U1.1@29.911,135.225 27.965,135.225 27.623,135.567 27.573,135.567 27.3,135.84 D1.2@27.3,135.89 D1.1@25.4,135.89
AGND: C18.2 C21.2 C22.2 C24.2 C29.2 C38.2 C41.2 C42.2 C44.2 C48.2 C58.2 C61.2 C62.2 C64.2 C68.2 NT2.1 NT4.1 NT5.1 R8.1 R18.1 R19.1 R28.1 R29.1 R36.1 U4.6 U4.13 U6.6 U6.13 U8.6 U8.13 | length 167.6
  Top Layer w0.254: C62.2@10.638,17.78 10.638,15.185 C61.2@10.185,14.732 10.174,14.732 9.523,14.081 9.523,14.07 9.144,13.691 9.144,10.541 9.398,10.287 10.522,10.287 C58.2@10.541,10.268 10.543,10.27 12.19,10.27 R28.1@12.192,10.272 12.365,10.445 12.746,10.445 14.058,11.757 v1(15.494,13.193) U8.6@17.272,13.193 ; C42.2@15.845,59.563 15.845,57.078 C41.2@16.408,56.515 15.875,55.982 15.875,53.086 16.51,52.451 C38.2@17.018,52.451 ; C22.2@15.845,98.806 15.845,96.067 C21.2@15.9,96.012 15.9,94.694 14.859,93.653 v1(14.859,92.583) 15.748,91.694 C18.2@16.383,91.694 16.391,91.686 18.026,91.686 R8.1@18.034,91.679 19.035,91.679 22.154,94.798 U4.6@23.847,94.798 ; C38.2@17.152,52.318 17.396,52.074 R18.1@18.796,52.074 19.816,52.074 21.886,54.144 U6.6@23.309,54.144 ; NT2.1@21.082,7.239 21.644,6.677 21.644,6.169 v1(21.717,6.096) 22.254,6.633 C68.2@22.254,7.747 22.145,7.856 22.145,11.677 22.303,11.835 23.114,11.835 U8.13@23.172,11.893 24.159,11.893 26.146,9.906 27.861,9.906 R29.1@28.321,10.366 28.478,10.366 28.956,10.844 28.956,13.007 C64.2@29.284,13.335 ; NT4.1@27.305,48.318 28.006,48.318 28.456,48.768 28.247,48.977 28.247,48.999 28.086,49.159 28.086,52.695 28.235,52.844 U6.13@29.209,52.844 30.214,52.844 32.448,50.609 R19.1@35.496,50.609 ; NT5.1@28.771,89.281 29.98,89.281 29.771,89.49 29.771,89.512 28.702,90.58 28.702,93.318 28.851,93.467 29.716,93.467 U4.13@29.747,93.498 31.089,93.498 33.782,90.805 35.433,90.805 R36.1@35.687,91.059 R36.1@35.832,91.059 ; C44.2@35.622,53.823 C44.2@35.597,53.848 35.597,51.784 34.994,51.181 R19.1@34.925,51.181 35.052,51.054 v1(37.592,51.054) ; C24.2@36.105,94.869 36.105,91.332 R36.1@35.832,91.059 ; v1(39.116,90.424) 38.481,91.059 R36.1@35.832,91.059
  Bottom Layer w0.254: v1(14.859,92.583) 16.383,91.059 38.481,91.059 v1(39.116,90.424) ; v1(15.494,13.193) 15.494,11.557 20.955,6.096 v1(21.717,6.096) ; v1(15.887,54.204) 17.17,54.204 20.32,51.054 v1(37.592,51.054)
buck1_COMP: C14.2 C17.2 U4.9 | length 7.7
  Top Layer w0.254: C14.2@21.578,89.408 C14.2@21.709,89.277
  Top Layer w0.45: C14.2@21.578,89.408 21.578,91.555 22.871,92.848 U4.9@23.847,92.848 ; C17.2@21.709,86.741 C14.2@21.709,89.277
